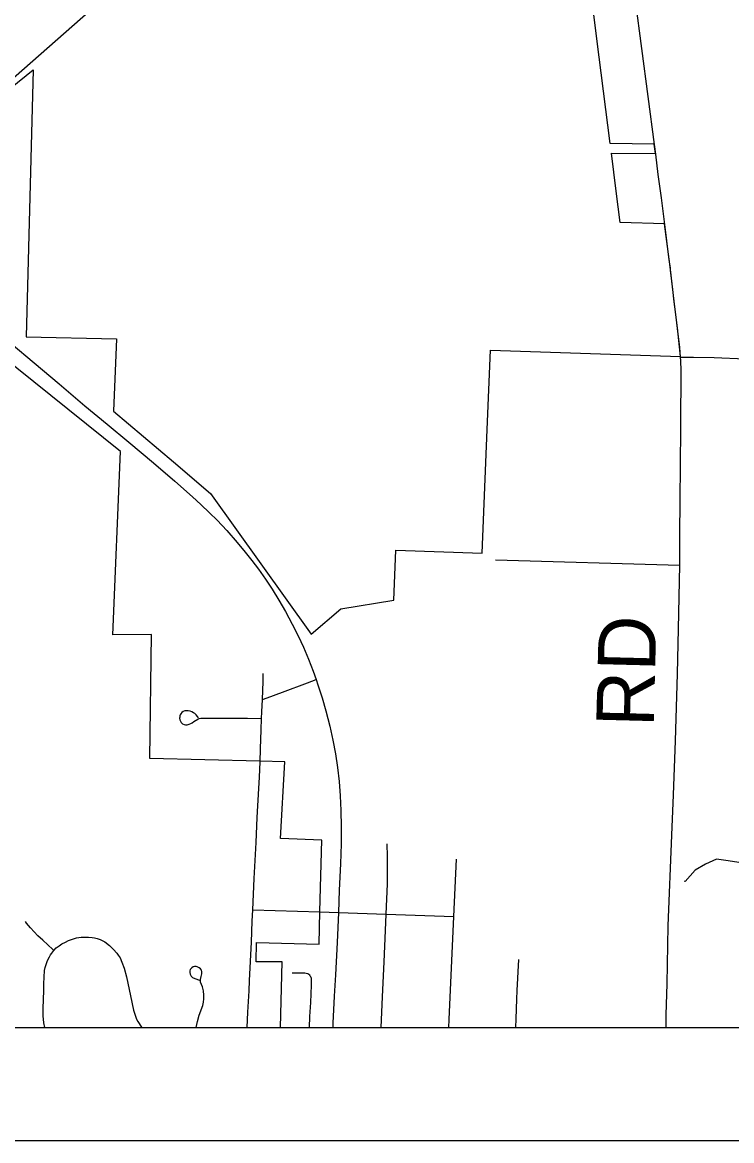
# Model space of a CAD drawing. Extents: x 0 to 34, y 0 to 22.
# Drawn here: x 16.998 to 17.698, y 9.81 to 10.914 of the extents above; entities that cross this region are included whole.
import ezdxf

# ---------------------------------------------------------------- set-up
doc = ezdxf.new("R2010")
doc.units = 0
for name, color, linetype in [('GM_X_City_Street', 7, 'Continuous'), ('GM_X_Corporation', 7, 'Continuous'), ('GM_X_County_Road', 7, 'Continuous'), ('GM_X_County_Road_Text', 7, 'Continuous'), ('GM_X_Minor_River', 7, 'Continuous'), ('GM_X_Rail_Line', 7, 'Continuous'), ('GM_X_State_Route', 7, 'Continuous'), ('GM_X_Township_Road', 7, 'Continuous'), ('SH_Data', 7, 'Continuous')]:
    doc.layers.add(name, color=color, linetype=linetype)

msp = doc.modelspace()

# ---------------------------------------------------------------- linework, layer by layer
at = {"layer": 'GM_X_City_Street'}
for points in [[(17.0287, 9.9975), (17.0277, 9.9986), (17.0177, 10.0077), (17.013, 10.012), (17.0092, 10.0159), (17.0056, 10.02), (17.0036, 10.0222), (17.0018, 10.0245), (17.0006, 10.0262)], [(17.0197, 9.9214), (17.0189, 9.9262), (17.0183, 9.9331), (17.0183, 9.9412), (17.0184, 9.948), (17.0185, 9.9516), (17.0187, 9.9553), (17.0188, 9.9645), (17.019, 9.9712), (17.0194, 9.9776), (17.02, 9.9808), (17.021, 9.9837), (17.0221, 9.9866), (17.0231, 9.9889), (17.0243, 9.9913), (17.0253, 9.9932), (17.0266, 9.995), (17.0287, 9.9975), (17.0311, 10), (17.034, 10.0021), (17.0366, 10.0039), (17.0403, 10.0058), (17.0433, 10.0072), (17.0481, 10.009), (17.0512, 10.01), (17.0558, 10.0106), (17.0601, 10.0108), (17.0629, 10.0108), (17.0665, 10.0104), (17.069, 10.0101), (17.0716, 10.0094), (17.0746, 10.0083), (17.079, 10.0059), (17.0836, 10.0025), (17.0877, 9.9986), (17.091, 9.9947), (17.0922, 9.993), (17.0941, 9.9901), (17.096, 9.9859), (17.0982, 9.9801), (17.1003, 9.9716), (17.1043, 9.9528), (17.1074, 9.9386), (17.1093, 9.9327), (17.1104, 9.9298), (17.1116, 9.9274), (17.1152, 9.9217), (17.1154, 9.9214)], [(17.1694, 9.9214), (17.1698, 9.9243), (17.1706, 9.9275), (17.1723, 9.9335), (17.1758, 9.9432), (17.1766, 9.9464), (17.177, 9.9497), (17.177, 9.9533), (17.1765, 9.9575), (17.1754, 9.9615), (17.1737, 9.9663), (17.1735, 9.969), (17.1741, 9.9717), (17.1749, 9.9746), (17.1749, 9.9767), (17.1744, 9.9782), (17.1735, 9.9795), (17.1722, 9.9805), (17.1704, 9.9815), (17.1692, 9.9817), (17.1677, 9.9817), (17.1662, 9.9813), (17.1649, 9.9804), (17.1635, 9.9787), (17.163, 9.9773), (17.1629, 9.9756), (17.1632, 9.9741), (17.1642, 9.9722), (17.1658, 9.9707), (17.1678, 9.9697), (17.1727, 9.9682)]]:
    msp.add_lwpolyline(points, dxfattribs=at)
at = {"layer": 'GM_X_Corporation'}
for points in [[(16.8496, 10.7389), (17.0084, 10.867), (17.0014, 10.6033), (17.0906, 10.6013), (17.0906, 10.6013), (17.0877, 10.5299), (17.1468, 10.4798), (17.1835, 10.4487), (17.2828, 10.3098), (17.3123, 10.3349), (17.3646, 10.3435), (17.3665, 10.3927), (17.4517, 10.3898), (17.4567, 10.512), (17.4599, 10.5901), (17.6476, 10.5839), (17.6467, 10.5933), (17.6446, 10.6121), (17.643, 10.6252), (17.6414, 10.6384), (17.6377, 10.6697), (17.6364, 10.68), (17.632, 10.7149), (17.5881, 10.7162), (17.5841, 10.7473), (17.5794, 10.7847), (17.623, 10.7843), (17.6217, 10.7937), (17.5782, 10.7942), (17.5652, 10.8976), (17.5522, 11.0011)], [(15.0302, 9.9214), (17.2525, 9.9214), (17.2543, 9.9862), (17.2284, 9.9863), (17.2289, 10.0053), (17.2909, 10.0036), (17.2914, 10.036), (17.2935, 10.1064), (17.2527, 10.1079), (17.257, 10.1838), (17.2323, 10.1844), (17.1236, 10.1869), (17.1253, 10.3096), (17.0869, 10.3091), (17.0946, 10.4902), (16.8206, 10.7101)], [(13.1219, 9.9214), (18.7033, 9.9214)]]:
    msp.add_lwpolyline(points, dxfattribs=at)
at = {"layer": 'GM_X_County_Road'}
msp.add_line((17.6232, 10.7837), (17.6219, 10.7931), dxfattribs=at)
for points in [[(17.6219, 10.7931), (17.6034, 10.9353), (17.5962, 10.9898), (17.5867, 11.0614)], [(17.6322, 10.7143), (17.6289, 10.7404), (17.6258, 10.7636), (17.6232, 10.7837)], [(17.6478, 10.5834), (17.6469, 10.5927), (17.6448, 10.6115), (17.643, 10.6255), (17.6416, 10.6378), (17.6402, 10.6501), (17.6379, 10.6691), (17.6377, 10.6715), (17.6366, 10.6794), (17.6322, 10.7143)], [(17.6469, 10.378), (17.6471, 10.4082), (17.6474, 10.4413), (17.6482, 10.5124), (17.6483, 10.5734), (17.6482, 10.5765), (17.648, 10.5798), (17.6478, 10.5834)], [(17.6478, 10.5834), (17.6526, 10.5834), (17.6606, 10.5834), (17.6811, 10.5829), (17.7116, 10.5817)], [(17.6334, 9.9214), (17.6336, 9.9338), (17.6344, 9.9647), (17.6356, 10.0219), (17.6393, 10.1112), (17.6409, 10.151), (17.6429, 10.2044), (17.6449, 10.2705), (17.6458, 10.3152), (17.6469, 10.378)]]:
    msp.add_lwpolyline(points, dxfattribs=at)
at = {"layer": 'GM_X_Minor_River'}
msp.add_lwpolyline([(17.7054, 10.0844), (17.6948, 10.0861), (17.6834, 10.0875), (17.6725, 10.0828), (17.6623, 10.0767), (17.6522, 10.0655), (17.6518, 10.0659)], dxfattribs=at)
at = {"layer": 'GM_X_Rail_Line'}
msp.add_lwpolyline([(16.6324, 10.5469), (16.66, 10.5712), (16.7205, 10.6242), (16.7826, 10.6785), (16.8342, 10.7235), (16.9227, 10.8012), (17.0739, 10.9338), (17.1834, 11.0297), (17.2552, 11.0928), (17.2974, 11.1294), (17.4129, 11.2308), (17.4633, 11.2749), (17.5282, 11.3319), (17.5938, 11.3893), (17.6288, 11.4198), (17.6553, 11.4431), (17.7218, 11.5012)], dxfattribs=at)
at = {"layer": 'GM_X_State_Route'}
for points in [[(16.9866, 10.5967), (17.0091, 10.5778), (17.0338, 10.557), (17.0593, 10.5352), (17.0813, 10.517), (17.1027, 10.4992), (17.1271, 10.4788), (17.1481, 10.461), (17.1658, 10.4453), (17.1738, 10.4378), (17.1826, 10.4296), (17.1901, 10.4222), (17.1995, 10.4121), (17.2097, 10.4004), (17.2176, 10.3908), (17.2242, 10.3824), (17.2307, 10.3739), (17.2377, 10.364), (17.2442, 10.3542), (17.2508, 10.3433), (17.2574, 10.332), (17.2642, 10.3196), (17.2702, 10.308), (17.2752, 10.297), (17.2802, 10.2852), (17.2848, 10.2733), (17.2877, 10.265)], [(17.2877, 10.265), (17.2896, 10.2598), (17.2938, 10.2468), (17.2974, 10.2342), (17.3012, 10.2191), (17.3043, 10.2051), (17.3068, 10.1916), (17.3088, 10.178), (17.3104, 10.1644), (17.3116, 10.1502), (17.3123, 10.1358), (17.3126, 10.1197), (17.3125, 10.1028), (17.3119, 10.0829), (17.3107, 10.0569), (17.3099, 10.0349)], [(17.3099, 10.0349), (17.3086, 10.0053), (17.307, 9.9736), (17.3057, 9.9524), (17.3044, 9.9257), (17.3042, 9.9214)]]:
    msp.add_lwpolyline(points, dxfattribs=at)
at = {"layer": 'GM_X_Township_Road'}
for p, q in [((17.4649, 10.3831), (17.6469, 10.378)), ((17.4239, 10.0311), (17.4264, 10.0878)), ((17.2253, 10.0377), (17.2916, 10.0355)), ((17.2916, 10.0355), (17.3099, 10.0349)), ((17.3099, 10.0349), (17.3571, 10.0333)), ((17.3571, 10.0333), (17.4239, 10.0311))]:
    msp.add_line(p, q, dxfattribs=at)
for points in [[(17.2347, 10.2452), (17.2354, 10.2629), (17.2356, 10.2708)], [(17.2347, 10.2452), (17.2395, 10.247), (17.2545, 10.2526), (17.2794, 10.2619), (17.2877, 10.265)], [(17.2339, 10.2265), (17.2343, 10.2332), (17.2347, 10.2452)], [(17.1716, 10.2273), (17.1707, 10.2285), (17.1694, 10.2302), (17.1681, 10.2313), (17.1668, 10.2322), (17.165, 10.2331), (17.1632, 10.2338), (17.1614, 10.2341), (17.1597, 10.2342), (17.158, 10.234), (17.1565, 10.2334), (17.1551, 10.2323), (17.1541, 10.2312), (17.1535, 10.2301), (17.1532, 10.2291), (17.153, 10.228), (17.1529, 10.227), (17.1532, 10.2253), (17.1537, 10.224), (17.1545, 10.2227), (17.1557, 10.2214), (17.1573, 10.2206), (17.1589, 10.2203), (17.1605, 10.2204), (17.1623, 10.2209), (17.1639, 10.2216), (17.1653, 10.2223), (17.1671, 10.2234), (17.171, 10.2259), (17.1723, 10.2264), (17.1738, 10.2268), (17.1751, 10.2269), (17.1767, 10.2269), (17.1879, 10.2267), (17.1997, 10.2267), (17.2199, 10.2267), (17.2339, 10.2265)], [(17.2325, 10.1838), (17.2329, 10.1967), (17.2335, 10.2153), (17.2339, 10.2265)], [(17.2253, 10.0377), (17.2267, 10.0686), (17.2287, 10.104), (17.2296, 10.1289), (17.2312, 10.1575), (17.2317, 10.1686), (17.2325, 10.1838)], [(17.3584, 10.0744), (17.3584, 10.0792), (17.3583, 10.0868), (17.3582, 10.0915), (17.358, 10.1016), (17.358, 10.1029)], [(17.3571, 10.0333), (17.3583, 10.0632), (17.3584, 10.0724), (17.3584, 10.0744)], [(17.2196, 9.9214), (17.2204, 9.9365), (17.2216, 9.9578), (17.2221, 9.9677), (17.2238, 10.0056), (17.2247, 10.0263), (17.2253, 10.0377)], [(17.3519, 9.9214), (17.3532, 9.9516), (17.3549, 9.9863), (17.3562, 10.0173), (17.3571, 10.0333)], [(17.4188, 9.9214), (17.4192, 9.9295), (17.4239, 10.0311)], [(17.485, 9.9214), (17.4854, 9.9301), (17.4861, 9.9493), (17.4865, 9.9581), (17.488, 9.9887)], [(17.2813, 9.9214), (17.2817, 9.9324), (17.2824, 9.946), (17.2832, 9.9632), (17.2833, 9.9676), (17.2833, 9.9688), (17.2832, 9.9697), (17.2829, 9.9707), (17.2826, 9.9716), (17.282, 9.9723), (17.2815, 9.973), (17.2807, 9.9737), (17.2797, 9.9743), (17.2791, 9.9746), (17.2779, 9.9749), (17.2766, 9.975), (17.2757, 9.9751), (17.2641, 9.9751)]]:
    msp.add_lwpolyline(points, dxfattribs=at)
at = {"layer": 'SH_Data'}
msp.add_line((12.556, 9.8098), (19.556, 9.8098), dxfattribs=at)

# ---------------------------------------------------------------- texts
at = {"layer": 'GM_X_County_Road_Text'}
msp.add_text('RD', height=0.05682, rotation=88.541, dxfattribs=at).set_placement((17.6212, 10.2177))

doc.saveas('drawing.dxf')
